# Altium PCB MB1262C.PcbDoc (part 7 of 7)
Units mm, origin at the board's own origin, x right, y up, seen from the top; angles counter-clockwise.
Board outline 208 x 250 mm, 6 copper layers (Top Layer, Layer 2, Layer 3, Layer 4, Layer 5, Bottom Layer), stack 1.596 mm thick; 483 components, 502 nets, 2134 pads, 1709 vias.
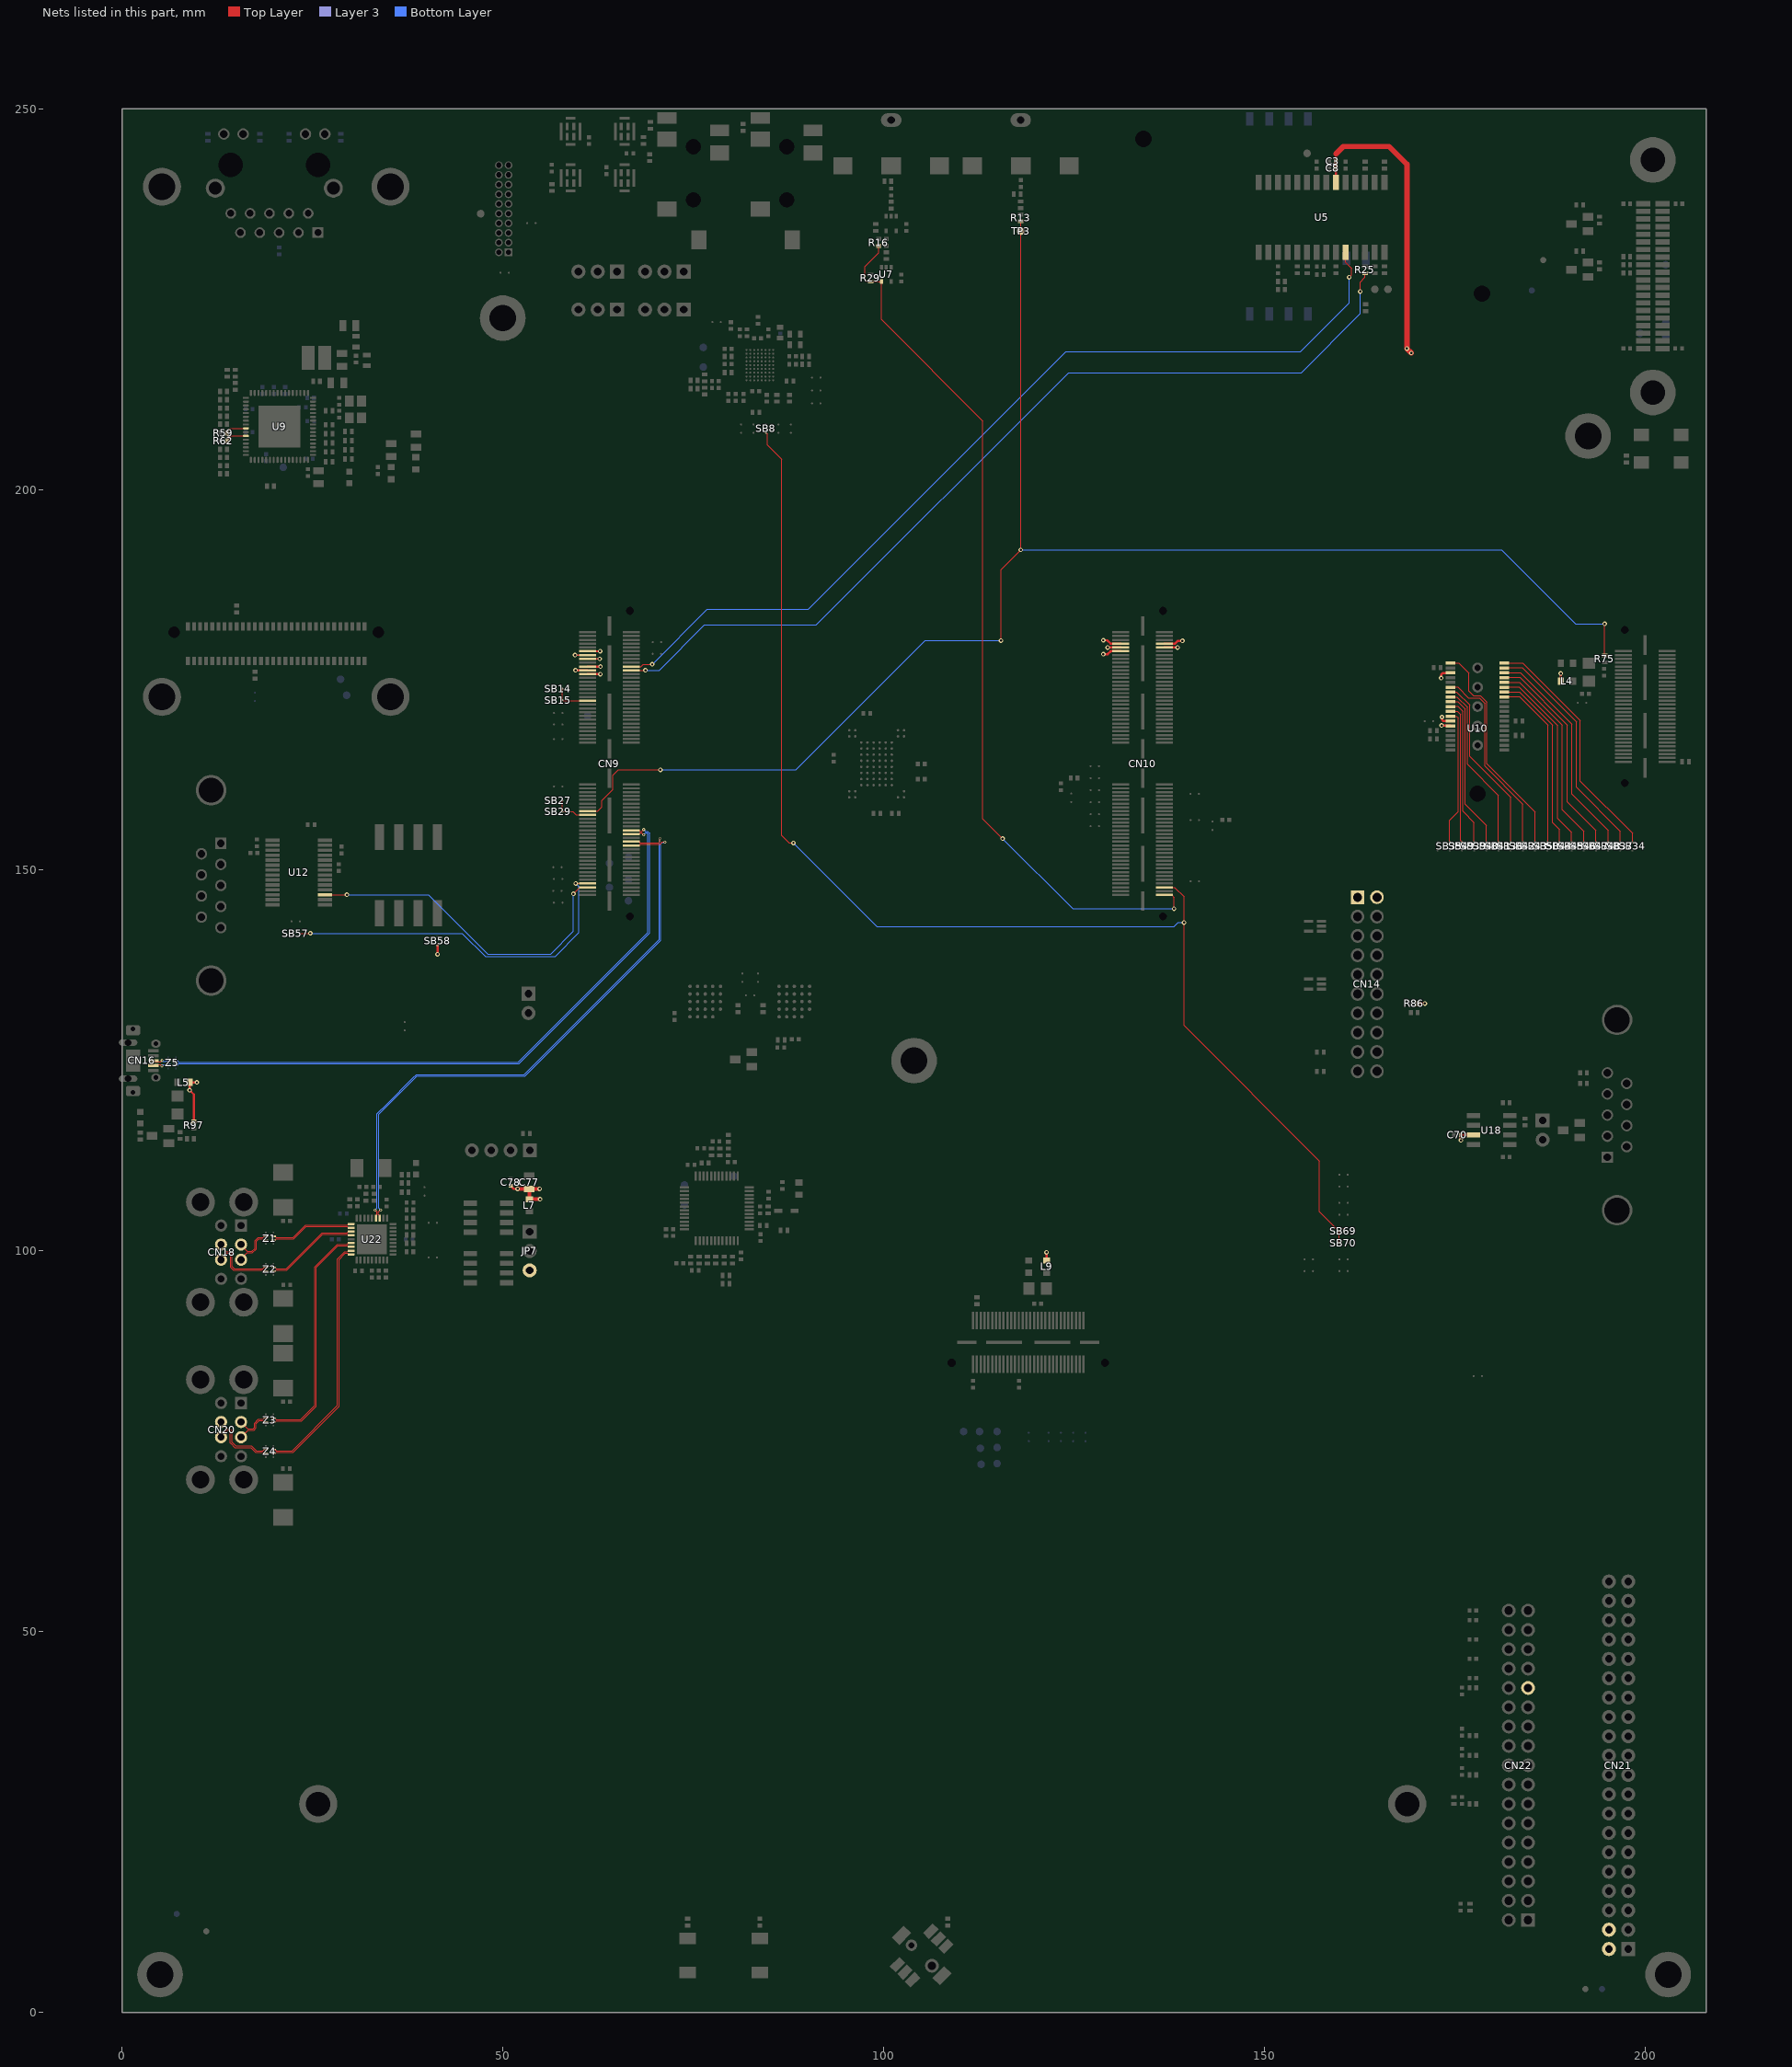
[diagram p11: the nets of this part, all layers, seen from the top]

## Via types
v1: diameter 0.6, hole 0.3, Top Layer to Bottom Layer, tented both sides, 979 vias
v2: diameter 0.55, hole 0.3, Top Layer to Bottom Layer, tented both sides, 687 vias
v3: diameter 0.3, hole 0.15, Top Layer to Bottom Layer, tented both sides, 31 vias
v4: diameter 0.4, hole 0.2, Top Layer to Bottom Layer, tented both sides, 12 vias

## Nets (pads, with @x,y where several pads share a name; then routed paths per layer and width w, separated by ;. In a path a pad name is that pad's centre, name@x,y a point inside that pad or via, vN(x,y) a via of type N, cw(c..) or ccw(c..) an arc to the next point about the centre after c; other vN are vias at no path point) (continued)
SAI2_SDB: CN10.116 SB8.1 SB69.2 SB70.2 | length 168.9
  Top Layer w0.1: SB8.1@84.556,207.434 84.733,207.257 84.733,205.858 86.63,203.961 86.63,154.542 87.605,153.567 v1(88.157,153.567) ; CN10.116@136.87,147.75 136.882,147.738 136.91,147.766 136.929,147.746 138.22,147.746 139.462,146.503 139.437,146.478 v1(139.437,143.128) 139.437,129.621 157.245,111.813 157.245,105.133 159.761,102.618 SB69.2@159.837,102.618 SB70.2@159.836,101.067 ; 160.36,102.937 160.409,102.985
  Bottom Layer w0.1: v1(88.157,153.567) 99.129,142.595 138.158,142.595 138.691,143.128 v1(139.437,143.128)
SAI4_SD_A: CN9.75 R13.1 R75.1 TP3.1 | length 206.1
  Top Layer w0.1: CN9.75@61.13,157.75 62.48,157.75 63.021,158.291 63.021,159.142 64.474,160.595 64.474,162.464 65.186,163.176 v1(70.703,163.176) ; v1(115.416,180.162) 115.416,189.478 v1(118.002,192.065) 118.002,202.486 118,202.489 TP3.1@118,233.925 R13.1@118,235.2 ; R75.1@194.675,178.2 v1(194.675,182.343)
  Bottom Layer w0.1: v1(70.703,163.176) 88.495,163.176 105.478,180.158 115.412,180.158 v1(115.416,180.162) ; v1(118.002,192.065) 181.136,192.065 190.858,182.343 v1(194.675,182.343)
SELRGV: R59.1 U9.25 | length 2.8
  Top Layer w0.1: R59.1@13.775,207.45 13.775,207.513 14.287,208.025 U9.25@16.275,208.025
SMARTCARD_CLK: CN9.20 U5.24 | length 121.1
  Top Layer w0.13: CN9.20@66.87,176.75 68.151,176.75 68.453,177.053 v1(69.618,177.053) ; U5.24@160.675,231.135 160.675,229.827 161.464,229.038 161.464,228.195 v1(161.128,227.86)
  Bottom Layer w0.13: v1(69.618,177.053) 76.843,184.278 90.095,184.278 123.932,218.115 154.743,218.115 161.128,224.5 v1(161.128,227.86)
SMARTCARD_IO: CN9.22 R25.2 | length 120.7
  Top Layer w0.1: CN9.22@66.87,176.25 68.723,176.25 v1(68.728,176.245) ; v1(162.576,226) 162.576,227.224 163.225,227.872 R25.2@163.225,228.4
  Bottom Layer w0.1: v1(68.728,176.245) 70.549,176.245 76.496,182.192 91.176,182.192 124.316,215.332 154.831,215.332 162.576,223.077 v1(162.576,226)
SPDIF_RX: CN10.120 R16.2 R29.2 U7.4 | length 116.4
  Top Layer w0.1: R16.2@99.35,231.975 99.35,231.09 97.531,229.271 97.531,227.554 97.744,227.341 98.259,227.341 R29.2@98.3,227.3 U7.4@99.7,227.3 99.7,222.301 113.026,208.974 113.026,156.758 v1(115.628,154.157) ; CN10.120@136.87,146.75 137.801,146.75 138.131,146.42 v1(138.131,144.936)
  Bottom Layer w0.1: v1(115.628,154.157) 124.849,144.936 v1(138.131,144.936)
TIM2_CH4: CN9.37 SB14.2 SB15.2 | length 4.9
  Top Layer w0.1: SB14.2@57.817,173.842 SB15.2@57.817,172.338 57.905,172.25 CN9.37@61.13,172.25
TIM12_CH1: CN9.77 SB27.2 SB29.2 | length 5
  Top Layer w0.1: SB27.2@57.817,159.163 SB29.2@57.817,157.692 59.209,157.692 59.651,157.25 CN9.77@61.13,157.25
TRACED0: SB43.2 U10.38 | length 29.2
  Top Layer w0.13: U10.38@174.47,177.215 175.505,177.215 176.82,175.9 176.82,173.543 177.428,172.935 178.348,172.935 179.224,172.059 179.224,163.961 185.526,157.659 SB43.2@185.526,153.692
TRACED1: SB42.2 U10.28 | length 25.6
  Top Layer w0.13: U10.28@174.455,174.025 174.47,174.04 175.382,174.04 176.792,172.63 178.205,172.63 178.886,171.949 178.95,171.885 178.95,163.668 183.926,158.692 SB42.2@183.926,153.692
TRACED2: SB36.2 U10.26 | length 23.4
  Top Layer w0.13: U10.26@174.47,173.405 175.231,173.405 176.943,171.693 176.943,164.932 182.326,159.548 SB36.2@182.326,153.692
TRACED3: SB41.2 U10.24 | length 22.2
  Top Layer w0.13: U10.24@174.455,172.755 175.301,172.755 176.654,171.402 176.654,163.914 180.726,159.841 SB41.2@180.726,153.692
TRACED4: SB40.2 U10.22 | length 20.9
  Top Layer w0.13: U10.22@174.47,172.135 174.487,172.118 175.394,172.118 176.336,171.177 176.336,158.659 179.126,155.868 SB40.2@179.126,153.692
TRACED5: SB39.2 U10.20 | length 19.6
  Top Layer w0.13: U10.20@174.455,171.485 174.47,171.5 175.382,171.5 176.047,170.836 176.047,157.748 177.526,156.269 SB39.2@177.526,153.692
TRACED6: SB49.2 U10.18 | length 18.4
  Top Layer w0.13: U10.18@174.394,170.871 174.429,170.906 U10.18@174.47,170.865 ; U10.18@174.455,170.85 175.312,170.85 175.747,170.415 175.747,153.871 SB49.2@175.926,153.692
TRACED7: SB35.2 U10.16 | length 17.9
  Top Layer w0.13: SB35.2@174.326,153.692 174.326,156.581 175.429,157.683 175.429,170.022 175.221,170.23 174.47,170.23 U10.16@174.455,170.215
TRACED8: SB34.2 U10.37 | length 31.9
  Top Layer w0.13: U10.37@181.53,177.215 183.881,177.215 191.461,169.635 191.461,161.706 198.326,154.841 SB34.2@198.326,153.692
TRACED9: SB37.2 U10.35 | length 30.5
  Top Layer w0.13: U10.35@181.53,176.58 183.851,176.58 190.962,169.47 190.962,160.897 196.726,155.132 SB37.2@196.726,153.692
TRACED10: SB48.2 U10.33 | length 29.1
  Top Layer w0.13: U10.33@181.53,175.945 183.621,175.945 190.386,169.18 190.386,159.974 195.126,155.233 SB48.2@195.126,153.692
TRACED11: SB47.2 U10.31 | length 27.8
  Top Layer w0.13: U10.31@181.53,175.31 183.544,175.31 189.771,169.083 189.771,158.969 193.526,155.214 SB47.2@193.526,153.692
TRACED12: SB46.2 U10.29 | length 26.6
  Top Layer w0.13: U10.29@181.53,174.675 183.495,174.675 189.116,169.054 189.116,163.688 ; 189.117,163.869 189.117,157.919 191.926,155.11 SB46.2@191.926,153.692
TRACED13: SB45.2 U10.27 | length 25.1
  Top Layer w0.13: U10.27@181.53,174.04 183.444,174.04 188.481,169.003 188.481,156.823 190.326,154.978 SB45.2@190.326,153.692
TRACED14: SB44.2 U10.25 | length 23.8
  Top Layer w0.13: U10.25@181.53,173.405 183.487,173.405 187.846,169.046 187.846,156.233 188.726,155.352 SB44.2@188.726,153.692
TRACED15: SB50.2 U10.23 | length 22.6
  Top Layer w0.13: U10.23@181.53,172.77 183.495,172.77 187.211,169.054 187.211,153.777 SB50.2@187.126,153.692
TXDLY: R62.1 U9.27 | length 2.8
  Top Layer w0.1: R62.1@13.775,206.375 13.775,206.442 14.358,207.025 U9.27@16.275,207.025
UART4_RX: CN9.115 U12.17 | length 44.3
  Top Layer w0.1: U12.17@26.65,146.775 26.655,146.78 26.797,146.639 26.952,146.793 v1(29.543,146.793) ; v1(59.279,146.896) 60.133,147.75 CN9.115@61.13,147.75
  Bottom Layer w0.1: v1(29.543,146.793) 40.207,146.793 48,139 56.3,139 59.279,141.979 v1(59.279,146.896)
UART4_TX: CN9.113 SB57.1 | length 47.4
  Top Layer w0.1: SB57.1@23.35,141.725 v1(24.736,141.725) ; v1(59.579,148.25) CN9.113@61.13,148.25
  Bottom Layer w0.1: v1(24.736,141.725) 44.675,141.725 47.7,138.7 56.9,138.7 60,141.8 60,147.829 v1(59.579,148.25)
USB1CN25_N: CN18.T2 Z1.2 | length 5.1
  Top Layer w0.1: CN18.T2@15.63,100.85 15.63,100.768 16.451,99.947 17.04,99.947 17.444,100.351 17.444,101.346 17.867,101.769 18.51,101.769 18.665,101.924 Z1.2@18.892,101.924
USB1CN25_P: CN18.T3 Z1.3 | length 5.1
  Top Layer w0.1: CN18.T3@15.704,98.85 15.704,99.01 16.451,99.757 17.119,99.757 17.634,100.272 17.634,101.267 17.946,101.579 18.517,101.579 18.672,101.424 Z1.3@18.892,101.424
  Bottom Layer w0.1: CN18.T3@15.63,98.85 CN18.T3@15.704,98.85
USB2CN25_N: CN18.B2 Z2.2 | length 8.5
  Top Layer w0.1: CN18.B2@13.01,100.85 13.01,100.618 13.694,99.934 14.191,99.934 14.47,99.654 14.47,97.944 14.721,97.694 18.524,97.694 18.679,97.849 Z2.2@18.892,97.849
  Bottom Layer w0.1: CN18.B2@13.01,100.713 CN18.B2@13.01,100.85
USB2CN25_P: CN18.B3 Z2.3 | length 8.5
  Top Layer w0.1: CN18.B3@13.01,98.85 13.01,99.091 13.663,99.744 14.112,99.744 14.28,99.576 14.28,97.865 14.642,97.504 18.518,97.504 18.673,97.349 Z2.3@18.892,97.349
  Bottom Layer w0.1: CN18.B3@13.01,98.85 CN18.B3@13.01,98.928
USB3CN26_N: CN20.T2 Z3.2 | length 4.5
  Top Layer w0.1: CN20.T2@15.63,77.55 16.518,76.662 17.243,76.662 17.408,76.827 17.408,77.394 17.921,77.907 18.518,77.907 18.673,78.062 Z3.2@18.892,78.062
USB3CN26_P: CN20.T3 Z3.3 | length 4.6
  Top Layer w0.1: CN20.T3@15.63,75.55 16.552,76.472 17.321,76.472 17.598,76.749 17.598,77.315 18,77.717 18.503,77.717 18.658,77.562 Z3.3@18.892,77.562
USB4CN26_N: CN20.B2 Z4.2 | length 8.4
  Top Layer w0.1: CN20.B2@13.01,77.55 13.01,77.442 13.803,76.65 14.15,76.65 14.425,76.375 14.425,74.88 14.916,74.389 17.013,74.389 17.62,73.782 18.504,73.782 18.659,73.937 Z4.2@18.892,73.937
USB4CN26_P: CN20.B3 Z4.3 | length 8.5
  Top Layer w0.1: CN20.B3@13.01,75.55 13.01,75.667 13.803,76.46 14.071,76.46 14.235,76.296 14.235,74.801 14.283,74.753 14.837,74.199 16.935,74.199 17.541,73.592 18.505,73.592 18.66,73.437 Z4.3@18.892,73.437
USB_AB_N: CN9.86 Z5.7 | length 85.3
  Top Layer w0.1: CN9.86@66.87,155.25 66.926,155.194 67.917,155.194 68.016,155.095 68.234,155.095 68.488,155.349 v4(68.488,155.354)
  Bottom Layer w0.1: Z5.7@7.074,124.463 7.305,124.463 7.424,124.582 52.109,124.582 69.258,141.731 69.258,154.842 69.007,155.093 68.726,155.093 68.493,155.325 v4@68.463,155.325 ; v4(68.488,155.354) 68.488,155.35 v4@68.463,155.325 ; v4@68.463,155.325 68.453,155.336 68.442,155.325 v4@68.463,155.325
USB_AB_P: CN9.88 Z5.6 | length 84.7
  Top Layer w0.1: CN9.88@66.87,154.75 66.948,154.828 67.96,154.828 68.037,154.905 68.217,154.905 68.478,154.644 v4@68.481,154.648 ; v4(68.481,154.643) v4@68.481,154.648 ; v4@68.488,154.655 v4@68.481,154.648
  Bottom Layer w0.1: Z5.6@7.074,124.963 7.27,124.963 7.46,124.772 52.03,124.772 69.068,141.81 69.068,154.763 68.929,154.903 68.731,154.903 v4@68.481,154.653 ; v4@68.47,154.655 v4@68.472,154.653 ; v4(68.481,154.643) v4@68.481,154.653 ; v4@68.472,154.653 68.477,154.648 v4@68.481,154.653 ; v4@68.472,154.653 68.484,154.664 68.488,154.66 v4@68.481,154.653
USB_CON_N: CN16.2 Z5.2 | length 2.2
  Top Layer w0.1: CN16.2@4.152,124.33 4.326,124.504 5.05,124.504 v4@5.241,124.313
  Bottom Layer w0.1: v4(5.247,124.313) 5.445,124.512 6.026,124.512 Z5.2@6.074,124.463
USB_CON_P: CN16.3 Z5.3 | length 2.2
  Top Layer w0.1: CN16.3@4.125,125 4.27,124.855 5.058,124.855 v4@5.249,125.046
  Bottom Layer w0.1: v4(5.249,125.034) 5.374,124.91 6.022,124.91 Z5.3@6.074,124.963
USB_HUB_N: CN9.94 U22.30 | length 78.5
  Top Layer w0.1: U22.30@33.825,104.3 33.825,104.625 33.67,104.78 33.67,105.12 33.925,105.375 v4(33.95,105.375) ; CN9.94@66.87,153.25 67.9,153.25 68.057,153.407 70.651,153.407 70.929,153.684 70.928,153.686 71.258,153.686 v4(71.261,153.683)
  Bottom Layer w0.1: v4(33.95,105.375) 33.685,105.64 33.685,117.941 38.737,122.993 52.896,122.993 70.717,140.814 70.717,153.458 70.941,153.683 v4(71.261,153.683) ; v4@71.198,153.744 71.244,153.744 71.198,153.79 v4@71.198,153.744
USB_HUB_P: CN9.92 U22.31 | length 78.2
  Top Layer w0.1: v4(33.23,105.375) 33.25,105.375 33.48,105.145 33.48,104.78 33.325,104.625 U22.31@33.325,104.3 ; CN9.92@66.87,153.75 67.881,153.75 68.034,153.597 70.515,153.597 70.64,153.721 70.64,153.791 ; 70.641,153.792 v4(70.641,154.159)
  Bottom Layer w0.1: v4(33.23,105.375) 33.495,105.64 33.495,109.667 33.495,118.019 34.784,119.308 38.186,122.71 38.658,123.183 52.817,123.183 70.527,140.892 70.527,153.578 70.641,153.693 v4(70.641,154.159)
USBDN1_N: U22.1 Z1.7 | length 11
  Top Layer w0.1: Z1.7@19.892,101.924 20.103,101.924 20.257,101.769 22.473,101.769 24.099,103.395 29.574,103.395 29.729,103.55 U22.1@30.075,103.55
USBDN1_P: U22.2 Z1.6 | length 11
  Top Layer w0.1: Z1.6@19.892,101.424 20.109,101.424 20.264,101.579 22.551,101.579 24.177,103.205 29.57,103.205 29.725,103.05 U22.2@30.075,103.05
USBDN2_N: U22.3 Z2.7 | length 12.2
  Top Layer w0.1: Z2.7@19.97,97.857 20.073,97.857 20.24,97.69 21.578,97.69 26.284,102.395 29.57,102.395 29.725,102.55 U22.3@30.075,102.55
USBDN2_P: U22.4 Z2.6 | length 12.2
  Top Layer w0.1: Z2.6@19.961,97.345 20.101,97.345 20.255,97.5 21.657,97.5 26.362,102.205 29.595,102.205 29.75,102.05 U22.4@30.075,102.05
USBDN3_N: U22.6 Z3.7 | length 30.5
  Top Layer w0.1: Z3.7@19.892,78.062 20.092,78.062 20.272,77.882 23.468,77.882 25.307,79.721 25.307,97.937 28.265,100.895 29.563,100.895 29.718,101.05 U22.6@30.075,101.05
USBDN3_P: U22.7 Z3.6 | length 30.5
  Top Layer w0.1: Z3.6@19.892,77.562 20.106,77.562 20.236,77.692 23.547,77.692 25.497,79.642 25.497,97.858 28.344,100.705 28.943,100.705 29.564,100.705 29.719,100.55 U22.7@30.075,100.55
USBDN4_N: U22.8 Z4.7 | length 32.4
  Top Layer w0.1: Z4.7@19.892,73.937 20.1,73.937 20.26,73.777 22.374,73.777 28.301,79.704 28.301,98.953 29.243,99.895 29.573,99.895 29.728,100.05 U22.8@30.075,100.05
USBDN4_P: U22.9 Z4.6 | length 32.4
  Top Layer w0.1: Z4.6@19.892,73.437 20.104,73.437 20.253,73.587 22.452,73.587 28.491,79.625 28.491,98.874 29.321,99.705 29.589,99.705 29.744,99.55 U22.9@30.075,99.55
VBUS_OTG: CN9.11 CN9.13 CN9.15 L5.1 R97.2 | length 11.3
  Top Layer w0.2: v1(59.485,178.25) CN9.13@61.13,178.25 ; CN9.15@61.13,177.75 v1(62.719,177.75) ; CN9.11@61.13,178.75 v1(62.77,178.75)
  Top Layer w0.3: R97.2@9.42,116.928 9.436,116.944 9.436,120.561 v1(8.874,121.122) L5.1@8.874,122.143 v1(9.828,122.143)
VBUS_SW: CN9.19 CN9.21 CN9.23 JP7.3 | length 5
  Top Layer w0.3: v1(59.535,176.25) CN9.21@61.13,176.25 ; CN9.23@61.13,175.75 v1(62.812,175.75) ; CN9.19@61.13,176.75 v1(62.825,176.75)
VDD: CN10.8 CN10.10 CN14.1 CN14.2 R86.1 U10.12 U10.14 U10.34 | length 10.1
  Top Layer w0.3: CN10.10@136.87,179.25 136.873,179.253 v1(138.607,179.253) ; CN10.8@136.87,179.75 138.265,179.75 138.63,180.115 139.153,180.115 v1@139.225,180.187 ; v1@139.192,180.22 v1@139.225,180.187 ; v1(139.226,180.111) v1@139.226,180.186 ; R86.1@170.125,132.5 v1(171.059,132.5) ; v1(173.195,175.238) 173.195,175.658 173.423,175.886 174.48,175.886 174.505,175.91 U10.34@174.47,175.945 ; v1(173.26,169.01) 174.42,169.01 U10.12@174.47,168.96 ; v1(173.311,170.111) 173.311,169.755 173.471,169.595 U10.14@174.47,169.595 ; v1@139.225,180.187 v1@139.226,180.186 ; v1@139.225,180.187 139.226,180.188 v1@139.226,180.186
  Layer 3 w0.3: v1(138.607,179.253) v1@138.618,179.242 ; v1@173.192,175.235 v1(173.195,175.238) ; v1@173.26,170.06 v1(173.311,170.111)
VIN: C3.2 C8.2 C70.2 C77.2 C78.2 CN10.7 CN10.9 CN10.11 CN21.2 CN21.4 CN22.25 L4.2 L7.1 L9.1 SB58.2 U5.6 U18.3 | length 58.6
  Top Layer w0.3: v1(41.425,138.955) SB58.2@41.425,140.15 ; C78.2@51.041,108.557 51.45,108.147 v1@51.96,108.147 ; L9.1@121.4,98.75 v1@121.4,99.786 ; v1(128.835,180.197) 129.354,180.197 129.8,179.75 CN10.7@131.13,179.75 ; v1(128.843,178.363) 129.426,178.363 129.813,178.75 CN10.11@131.13,178.75 ; v1(129.418,179.253) 131.133,179.253 CN10.9@131.13,179.25 ; 159.4,243.983 C8.2@159.4,242.175 159.405,242.17 U5.6@159.405,240.315 ; v1(175.796,114.524) 175.775,114.545 C70.2@175.775,115.25 177.44,115.25 U18.3@177.45,115.24 ; v1(188.907,175.834) 188.925,175.817 L4.2@188.925,174.825
  Top Layer w0.5: v1(51.94,108.15) C77.2@53.458,108.15 C77.2@53.48,108.15 ; C77.2@53.498,108.223 53.48,108.205 C77.2@53.48,108.15 ; v1(54.828,108.15) C77.2@53.48,108.15 ; v1(54.888,106.8) L7.1@53.48,106.8 C77.2@53.48,108.15 ; 159.4,243.983 159.402,243.985 159.402,244.067
  Top Layer w0.7: 159.402,244.067 160.359,245.024 166.375,245.024 168.704,242.695 v1(168.704,218.491) v1(169.283,217.912)
  other v1: 121.4,99.82
pads on no net: B1.MT1 B1.MT2 CN3.17 CN3.18 CN4.5 CN4.7 CN4.MT1 CN4.MT2 CN5.5 CN5.7 CN5.MT1 CN5.MT2 CN6.3 CN6.5 CN6.9 CN6.11 CN6.15 CN6.17 CN6.21 CN6.27 CN6.29 CN6.30 CN6.33 CN6.35 CN6.39 CN6.41 CN6.45 CN6.47 CN6.NHP2 CN6.NPH1 CN6.PTH1 CN6.PTH2 CN6.PTH3 CN6.PTH4 CN8.8 CN8.9 CN8.11 CN8.13 CN8.14 CN8.15 CN8.16 CN8.17 CN8.18 CN9.14 CN9.16 CN9.18 CN9.35 CN9.55 CN9.67 CN9.73 CN9.83 CN9.85 CN9.102 CN9.106 CN9.110 CN9.114 CN9.117 CN9.118 CN9.119 CN9.129 CN9.130 CN10.1 CN10.3 CN10.5 CN10.6 CN10.12 CN10.13 CN10.18 CN10.19 CN10.21 CN10.22 CN10.23 CN10.25 CN10.92 CN10.94 CN10.119 CN10.129 CN10.130 CN11.3 CN11.5 CN11.8 CN11.11 CN11.12 CN11.15 CN11.16 CN11.19 CN11.20 CN11.32 CN11.35 CN11.36 CN11.43 CN11.44 CN11.45 CN11.52 CN11.59 CN11.65 CN11.66 CN12.1 CN12.4 CN12.7 CN12.9 CN13.2 CN13.6 CN15.1 CN15.4 CN15.8 CN16.11 CN16.12 CN19.2 CN19.20 CN19.22 CN19.24 CN19.25 CN19.26 CN19.28 CN19.30 CN19.31 CN19.33 CN19.34 CN19.35 CN19.37 CN19.38 CN19.39 CN19.41 CN19.42 CN19.43 CN19.45 CN19.47 CN19.51 CN19.55 CN19.59 CN19.65 CN19.66 CN19.PTH3 CN19.PTH4 CN23.11 CN23.12 CN23.C6 MIRE1.1 MIRE2.1 MIRE3.1 MIRE4.1 MIRE5.1 MIRE6.1 U1.6 U1.7 U1.8 U2.6 U2.7 U2.8 U3.6 U3.7 U3.8 U4.6 U4.7 U4.8 U5.25 U6.1 U7.1 U8.A6 U8.A8 U8.B1 U8.B4 U8.B7 U8.B8 U8.C3 U8.C4 U8.C7 U8.C8 U8.F5 U8.F6 U8.F8 U8.F9 U8.G4 U8.H3 U8.H4 U8.H5 U9.16 U9.17 U9.32 U9.43 U9.44 U9.45 U9.46 U9.47 U10.1 U10.2 U10.3 U10.4 U10.MT6 U11.A1 U11.A2 U11.A9 U11.A10 U11.B1 U11.B9 U11.B10 U11.D6 U11.D7 U11.D8 U11.E3 U11.E4 U11.E5 U11.E6 U11.E7 U11.E8 U11.F3 U11.F4 U11.F5 U11.F6 U11.F7 U11.F8 U11.G3 U11.G5 U11.G6 U11.G7 U11.G8 U11.H3 U11.H5 U11.H6 U11.H7 U11.J3 U11.J5 U11.L1 U11.L2 U11.L9 U11.L10 U11.M1 U11.M2 U11.M9 U11.M10 U12.4 U12.8 U12.9 U12.11 U12.12 U12.14 U12.15 U12.16 U12.18 U12.19 U12.20 U12.21 U13.1 U13.3 U14.A2 U14.A3 U14.A5 U14.B1 U14.B5 U14.C1 U14.C3 U14.C5 U14.D1 U14.D5 U14.E1 U14.E2 U14.E3 U14.E4 U14.E5 U15.A2 U15.A3 U15.A5 U15.B1 U15.B5 U15.C1 U15.C3 U15.C5 U15.D1 U15.D5 U15.E1 U15.E2 U15.E3 U15.E4 U15.E5 U20.3 U20.4 U20.5 U20.6 U20.25 U20.32 U20.38 U20.41 X1.2 X1.4
copper on no net: | length 0.8
  Top Layer w0.3: v1(19.041,197.738) 19.041,198.514

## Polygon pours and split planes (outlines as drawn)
GND on Top Layer "gnd_top" (solid, remove dead copper, pour order 76): 208,250 0,250 0,0 208,0
1V05_GMII on Top Layer "1V05_GMII_L01_P031" (solid, pour order 31): 32.668,219.514 33.129,219.052 33.129,217.286 32.864,217.021 27.69,217.021 27.69,218.975 28.229,219.514
2V8 on Layer 4 "2V8_L04_P038" (solid, pour order 38): 64.247,237.407 64.247,178.615 64.247,178.325 64.661,177.912 65.143,177.429 67.076,177.429 81.5,191.854 81.5,220 94.536,233.036 185.643,233.036 192.15,226.529 197.543,226.529 197.543,217.402 198.167,216.778 203.607,216.778 206.703,219.874 206.703,244.627 203.379,247.95 74.771,247.95
1V8 on Layer 4 "1V8_L04_P034" (solid, pour order 34): 197.881,204.185 198.608,204.913 198.608,209.579 197.192,210.995 197.192,218.286 202.311,223.405 202.311,232.386 202.311,237.616 201.089,238.838 197.965,238.838 195.948,236.822 195.948,228.051 194.101,226.204 191.899,226.204 185.717,232.386 94.661,232.386 81.882,219.607 81.882,203.636 107.874,177.645 108.985,176.534 108.985,176.02 108.973,105.815 108.973,82 110.671,80.302 113.564,80.302 118.48,85.218 118.48,127.957 118.48,176.249 123.254,181.023 136.364,181.023 137.274,180.114 138.384,180.114 140.554,182.284 161.19,182.284 163.279,184.372 163.279,217.667 165.664,220.052 174.509,220.052 190.225,204.185
VIN on Layer 4 "VIN_L04_P039" (solid, pour order 39): 166.053,219.008 174.254,219.008 205.213,188.049 205.213,123.454 205.213,0.558 95.732,0.558 56.216,40.073 56.216,105.286 40.778,120.724 40.778,139.019 41.725,139.967 49.53,139.967 110.123,79.373 113.663,79.373 119.317,85.027 119.317,176.108 123.051,179.842 123.738,180.529 130.765,180.529 136.192,180.529 138.616,178.106 141.427,178.106 158.454,161.078 158.454,159.514 158.454,138.131 159.06,137.525 166.332,130.253 170.921,130.253 173.431,130.253 175.249,132.071 175.163,132.158 175.163,177.348 164.296,188.215 164.296,217.25
1V05_DVDD_GMII on Layer 4 "1V05_DVDD_GMII_L04_P063" (solid, pour order 63): 16.759,203.984 16.268,203.494 16.268,201.325 21.098,196.494 37.291,196.494 40.423,199.626 40.423,210.13 33.686,216.866 33.386,216.866 32.118,216.866 31.717,216.466 31.65,216.399 31.65,210.128 35.24,206.539 35.24,202.416 34.814,201.99 33.05,201.99 31.917,203.123 20.184,203.123 19.322,203.984
VDD on Layer 4 "VDD_L04_P037" (solid, pour order 37): 140.495,181.778 169.105,181.778 174.054,176.829 174.054,132.853 173.302,132.101 172.818,131.617 170.506,131.617 170.237,131.617 169.108,132.746 167.334,134.52 167.334,141.455 167.334,142.799 166.098,144.035 165.028,145.105 160.62,145.105 159.573,146.152 159.573,160.775 144.432,175.915 141.643,178.705 138.854,178.705 138.531,178.705 138.181,179.055 138.181,179.464
VBUS_OTG on Layer 4 "VBUS_OTG_L04_P055" (solid, pour order 55): 8.489,123.493 7.997,123.004 7.997,121.148 8.461,120.685 8.917,120.685 58.756,170.524 58.756,176.744 59.147,177.135 59.38,177.368 63.008,177.368 63.428,177.789 63.428,177.851 63.428,179.159 62.524,180.063 59.858,180.063 8.628,128.833 8.628,124.787 8.628,123.633
VBUS_SW on Layer 4 "VBUS_SW_L04_P047" (solid, pour order 47): 52.273,94.628 54.313,94.628 55.606,95.921 55.606,105.055 55.239,105.422 40.127,120.534 40.127,123.182 40.127,141.069 63.58,164.523 63.58,176.678 63.192,177.066 59.64,177.066 59.116,176.542 59.116,170.229 30.98,142.094 30.98,119.559 44.711,105.828 47.48,105.828 48.714,104.594 48.714,97.706
3V3_AVDD_GMII on Layer 4 "3V3_AVDD_GMII_L04_P033" (solid, pour order 33): 20.178,212.155 21.803,210.53 22.815,210.53 24.208,210.53 24.231,210.507 24.877,209.861 24.877,209.027 25.624,208.28 32.923,208.28 34.915,206.288 34.915,202.592 34.721,202.398 33.09,202.398 32.775,202.713 32.008,203.48 20.458,203.48 18.923,205.016 18.923,211.308 19.77,212.155
1V05_AVDD_GMII on Layer 4 "1V05_AVDD_GMII_L04_P062" (solid, pour order 62): 31.057,219.675 31.057,209.329 30.32,208.592 25.68,208.592 25.171,209.101 25.171,210.039 24.351,210.859 21.916,210.859 20.32,212.455 19.622,212.455 18.637,211.47 18.086,211.47 17.871,211.685 17.871,213.364 28.047,223.54 28.081,223.573 31.418,223.573 32.553,222.439 32.553,221.171
NetC99_2 on Layer 4 "NETC99_2_L04_P053" (solid, pour order 53): 46.212,105.454 47.18,105.454 48.052,104.582 48.052,101.686 36.732,90.366 35.362,90.367 19.41,90.367 16.746,93.031 16.746,99.937 16.746,105.752 16.059,106.439 15.933,106.565 15.296,106.565 14.395,105.665 14.395,102.813 13.779,102.197 12.388,102.197 11.775,102.81 11.775,103.044 11.775,109.688 12.757,110.671 13.202,111.115 17.612,111.115 18.665,111.115 20.419,109.361 20.419,105.709 19.303,104.593 19.303,98.799 22.768,95.334 37.784,95.334 45.131,102.681 45.131,104.46 45.685,105.014 46.125,105.454 46.265,105.454
NetC76_1 on Layer 4 "NETC76_1_L04_P051" (solid, pour order 51): 44.796,104.371 44.796,103.073 37.661,95.939 28.417,95.939 25.792,95.939 20.131,101.599 20.131,104.318 21.722,105.908 23.954,105.908 30.088,99.775 31.809,99.775 35.67,99.775 40.635,104.74 44.427,104.74
NetC102_1 on Layer 4 "NETC102_1_L04_P049" (solid, pour order 49): 45.138,96.984 45.138,93.79 29.51,78.162 20.865,78.162 20.776,78.162 19.921,79.017 19.921,80.347 21.611,82.037 28.777,82.037 43.374,96.633 44.264,97.523 44.609,97.523
NetC106_2 on Layer 4 "NETC106_2_L04_P045" (solid, pour order 45): 46.453,98.653 46.66,98.86 47.277,98.86 48.166,97.971 48.166,97.211 48.166,90.878 25.924,68.635 22.321,68.635 20.624,68.635 16.707,72.553 16.707,81.783 16.651,81.84 15.035,81.84 14.477,81.282 14.477,79.553 13.774,78.85 12.219,78.85 11.553,79.515 11.553,84.99 11.553,86.316 12.092,86.855 12.776,87.539 17.169,87.539 18.129,87.539 19.47,86.198 20.077,85.591 20.077,82.033 19.28,81.236 19.28,72.766 19.84,72.206 24.195,72.206 45.466,93.477 45.466,97.667
3V3 on Layer 3 "3V3_L03_P064" (solid, pour order 64): 205.737,247.986 205.737,4.658 205.737,2.461 2.993,2.461 2.993,6.677 2.993,244.446 2.993,247.986 6.533,247.986
3V3_DVDD_GMII on Layer 3 "3V3_DVDD_GMII_L03_P032" (solid, pour order 32): 39.17,241.972 39.17,205.268 34.054,200.152 12.414,200.152 9.502,203.064 9.502,244.013 11.968,246.478 34.663,246.478
GND on Bottom Layer "GND_L06_P073" (solid, remove dead copper, pour order 73): 208,250 208,0 0,0 0,59.478 0,250
NetC102_1 on Bottom Layer "NETC102_1_L06_P069" (solid, pour order 69): 23.614,81.667 23.614,80.62 22.043,79.049 16.351,79.049 16.172,79.228 16.172,81.086 19.592,81.086 20.502,81.997 23.284,81.997
NetC76_1 on Bottom Layer "NETC76_1_L06_P067" (solid, pour order 67): 23.756,105.382 23.756,104.066 21.965,102.276 14.945,102.276 14.692,102.529 14.692,104.563 19.763,104.563 20.978,105.778 23.361,105.778
GND on Layer 2 "GND_L02_P044" (solid, pour order 44): 0,250 0,0 208,0 208,250
GND on Layer 5 "GND_L05_P075" (solid, remove dead copper, pour order 75): 208,250 208,0 0,0 0,250

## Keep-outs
Keep-Out Layer:
  the board outline again, w0.1
  text "BOARD OUTLINE" at 83.125,-20.375 h1.9

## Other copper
Top Layer:
  text "1" at 12.773,4.071 h1
  text "1" at 96.4,-15.25 h2
  text "PRIMARY SIDE" at 82.11,-20.33 h2
Layer 4:
  text "4" at 15.315,4.09 h1
  text "4" at 96.4,-15.25 h2
  text "LAYER 4 (VCC PLANE)" at 82.11,-20.33 h2
Layer 5:
  text "5" at 16.319,4.105 h1
  text "5" at 96.4,-15.25 h2
  text "LAYER 5 (GND PLANE)" at 82.11,-20.33 h2
Layer 2:
  text "2" at 13.418,4.076 h1
  text "2" at 96.4,-15.25 h2
  text "LAYER 2 (GND PLANE)" at 82.11,-20.33 h2
Layer 3:
  text "3" at 14.374,4.066 h1
  text "3" at 96.4,-15.25 h2
  text "LAYER 3" at 82.11,-20.33 h2
Bottom Layer:
  text "6" at 17.926,4.097 h1
  text "6" at 96.4,-15.25 h2
  text "SECONDARY SIDE" at 82.11,-20.33 h2
Multi-Layer:
  circle w0.2: c-17,265.064 r3.442
  circle w0.2: c-17,265.064 r1.922
  circle w0.2: c231,266.063 r3.442
  circle w0.2: c231,266.063 r1.922
  circle w0.2: c226,-10.937 r3.442
  circle w0.2: c226,-10.937 r1.922
  pour cut-out: 12.303,5.554 12.303,3.554 18.691,3.554 18.691,5.554
  lines w0.2: -22.969,265 -10.967,265 ; -17,258.968 -17,270.969 ; 220.031,-11 232.033,-11 ; 225.031,266 237.033,266 ; 226,-17.033 226,-5.031 ; 231,259.967 231,271.969

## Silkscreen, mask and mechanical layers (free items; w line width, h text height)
Top Overlay:
  drawing of 1502 lines, arcs and shapes, not listed
  text "Headset" at 92.824,231.935 h2 r90
  text "2" at 47.569,230.544 h1.2
  text "Ethernet" at 12.067,229.006 h2
  text "Mems Micro" at 42.653,227.947 h2 r90
  text "Speaker_out" at 80.407,226.363 h2 r90
  text "SPDIF input" at 107.651,225.626 h2 r90
  text "Camera" at 206.407,224.212 h2 r90
  text "SPDIF output" at 123.496,223.781 h2 r90
  text "Trace" at 174.31,184.79 h2
  text "LTDC" at 196.561,182.912 h2
  text "Ethernet Module" at 9.225,171.956 h2
  text "2" at 173.26,164.005 h1.2
  text "UART4" at 2.813,163.83 h2
  text "I2C_EXT" at 32.434,158.131 h2
  text "JTAG" at 160.295,152.732 h2
  text "CAN FD" at 195.38,133.784 h2
  text "USB_OTG" at 6.213,124.209 h2
  text "MFX" at 44.875,115.15 h2
  text "USB_Host" at 3.655,109.569 h2
  text "DSI" at 103.916,87.357 h2
  text "USB_Host" at 3.348,65.469 h2
  text "Motor control" at 190.667,23.76 h2 r90
  text "GPIO expansion" at 202.043,22.112 h2 r90
  text "Joystick" at 99.289,13.027 h2
  text "Reset" at 75.359,12.156 h2
  text "2" at 177.761,9.864 h1.2
  text "STM32MP15X-EVAL" at 128.439,7.495 h2
  text "MB1262C" at 36.677,7.47 h2
  text "SILKSCREEN, (PRIMARY)" at 82.11,-20.33 h2
Bottom Overlay:
  lines w0.2: 50,22 60,22 77,22 77,32 50,32 50,22
  text "Smart Card" at 181.923,216.424 h2
  text "MB1262C" at 69.119,34.148 h2
  text "SILKSCREEN, (SECONDARY)" at 122.87,-20.33 h2
Top Paste:
  text "SOLDER PASTE, (PRIMARY)" at 82.11,-20.33 h2
Bottom Paste:
  text "SOLDER PASTE, (SECONDARY)" at 81.56,-20.33 h2
Top Solder:
  text "SOLDER MASK, (PRIMARY)" at 82.11,-20.33 h2
Bottom Solder:
  text "SOLDER MASK, (SECONDARY)" at 82.11,-20.33 h2
Mechanical 2:
  circle w0.2: c-17,265.064 r3.442
  circle w0.2: c-17,265.064 r1.922
  circle w0.2: c231,266.063 r3.442
  circle w0.2: c231,266.063 r1.922
  circle w0.2: c226,-10.937 r3.442
  circle w0.2: c226,-10.937 r1.922
  lines w0.2: -22.969,265 -10.967,265 ; -17,258.968 -17,270.969 ; 220.031,-11 232.033,-11 ; 225.031,266 237.033,266 ; 226,-17.033 226,-5.031 ; 231,259.967 231,271.969
Drill Drawing:
  drawing of 557 lines, arcs and shapes, not listed
  text "Layer" at 225.612,245.218 h2
  text "Name" at 236.954,245.218 h2
  text "Material" at 262.178,245.218 h2
  text "Thickness" at 283.993,245.218 h2
  text "Constant" at 300.962,245.218 h2
  text "Board Layer Stack" at 317.121,245.218 h2
  text "1" at 225.612,241.218 h2
  text "Top Overlay" at 236.954,241.218 h2
  text "2" at 225.612,237.218 h2
  text "Top Solder" at 236.954,237.218 h2
  text "Solder Resist" at 262.178,237.218 h2
  text "0,010mm" at 283.993,237.218 h2
  text "3,5" at 300.962,237.218 h2
  text "3" at 225.612,233.218 h2
  text "Top Layer" at 236.954,233.218 h2
  text "Copper" at 262.178,233.218 h2
  text "0,042mm" at 283.993,233.218 h2
  text "4" at 225.612,229.218 h2
  text "Dielectric 1" at 236.954,229.218 h2
  text "FR4" at 262.178,229.218 h2
  text "0,093mm" at 283.993,229.218 h2
  text "4,2" at 300.962,229.218 h2
  text "5" at 225.612,225.218 h2
  text "Layer 2" at 236.954,225.218 h2
  text "Copper" at 262.178,225.218 h2
  text "0,035mm" at 283.993,225.218 h2
  text "6" at 225.612,221.218 h2
  text "Dielectric 2" at 236.954,221.218 h2
  text "FR4" at 262.178,221.218 h2
  text "0,100mm" at 283.993,221.218 h2
  text "4,2" at 300.962,221.218 h2
  text "7" at 225.612,217.218 h2
  text "Layer 3" at 236.954,217.218 h2
  text "Copper" at 262.178,217.218 h2
  text "0,035mm" at 283.993,217.218 h2
  text "8" at 225.612,213.218 h2
  text "Dielectric 3" at 236.954,213.218 h2
  text "FR4" at 262.178,213.218 h2
  text "0,986mm" at 283.993,213.218 h2
  text "4,2" at 300.962,213.218 h2
  text "9" at 225.612,209.218 h2
  text "Layer 4" at 236.954,209.218 h2
  text "Copper" at 262.178,209.218 h2
  text "0,035mm" at 283.993,209.218 h2
  text "10" at 225.612,205.218 h2
  text "Dielectric 4" at 236.954,205.218 h2
  text "FR4" at 262.178,205.218 h2
  text "0,100mm" at 283.993,205.218 h2
  text "4,2" at 300.962,205.218 h2
  text "11" at 225.612,201.218 h2
  text "Layer 5" at 236.954,201.218 h2
  text "Copper" at 262.178,201.218 h2
  text "0,035mm" at 283.993,201.218 h2
  text "12" at 225.612,197.218 h2
  text "Dielectric 5" at 236.954,197.218 h2
  text "FR4" at 262.178,197.218 h2
  text "0,093mm" at 283.993,197.218 h2
  text "4,2" at 300.962,197.218 h2
  text "13" at 225.612,193.218 h2
  text "Bottom Layer" at 236.954,193.218 h2
  text "Copper" at 262.178,193.218 h2
  text "0,042mm" at 283.993,193.218 h2
  text "14" at 225.612,189.218 h2
  text "Bottom Solder" at 236.954,189.218 h2
  text "Solder Resist" at 262.178,189.218 h2
  text "0,010mm" at 283.993,189.218 h2
  text "3,5" at 300.962,189.218 h2
  text "15" at 225.612,185.218 h2
  text "Bottom Overlay" at 236.954,185.218 h2
  text "Symbol" at 228.045,161.77 h1.83
  text "Count" at 240.894,161.77 h1.83
  text "Hole Size" at 257.4,161.77 h1.83
  text "Plated" at 287.109,161.77 h1.83
  text "Hole Type" at 299.959,161.77 h1.83
  text "Via/Pad" at 318.597,161.77 h1.83
  text "Hole Length" at 333.579,161.77 h1.83
  text "Routed Path Length" at 362.019,161.77 h1.83
  text "31" at 240.894,157.96 h1.52
  text "0,150mm (5,91mil)" at 257.4,157.96 h1.52
  text "PTH" at 287.109,157.96 h1.52
  text "Round" at 299.959,157.96 h1.52
  text "Via" at 318.597,157.96 h1.52
  text "-" at 333.579,157.96 h1.52
  text "-" at 362.019,157.96 h1.52
  text "12" at 240.894,154.15 h1.52
  text "0,200mm (7,87mil)" at 257.4,154.15 h1.52
  text "PTH" at 287.109,154.15 h1.52
  text "Round" at 299.959,154.15 h1.52
  text "Via" at 318.597,154.15 h1.52
  text "-" at 333.579,154.15 h1.52
  text "-" at 362.019,154.15 h1.52
  text "1666" at 240.894,150.34 h1.52
  text "0,300mm (11,81mil)" at 257.4,150.34 h1.52
  text "PTH" at 287.109,150.34 h1.52
  text "Round" at 299.959,150.34 h1.52
  text "Via" at 318.597,150.34 h1.52
  text "-" at 333.579,150.34 h1.52
  text "-" at 362.019,150.34 h1.52
  text "2" at 240.894,146.53 h1.52
  text "0,600mm (23,62mil)" at 257.4,146.53 h1.52
  text "PTH" at 287.109,146.53 h1.52
  text "Slot" at 299.959,146.53 h1.52
  text "Pad" at 318.597,146.53 h1.52
  text "1,300mm (51,18mil)" at 333.579,146.53 h1.52
  text "0,700mm (27,56mil)" at 362.019,146.53 h1.52
  text "2" at 240.894,142.72 h1.52
  text "0,650mm (25,59mil)" at 257.4,142.72 h1.52
  text "PTH" at 287.109,142.72 h1.52
  text "Slot" at 299.959,142.72 h1.52
  text "Pad" at 318.597,142.72 h1.52
  text "0,850mm (33,47mil)" at 333.579,142.72 h1.52
  text "0,200mm (7,88mil)" at 362.019,142.72 h1.52
  text "20" at 240.894,138.91 h1.52
  text "0,700mm (27,56mil)" at 257.4,138.91 h1.52
  text "PTH" at 287.109,138.91 h1.52
  text "Round" at 299.959,138.91 h1.52
  text "Pad" at 318.597,138.91 h1.52
  text "-" at 333.579,138.91 h1.52
  text "-" at 362.019,138.91 h1.52
  text "1" at 240.894,135.1 h1.52
  text "0,800mm (31,50mil)" at 257.4,135.1 h1.52
  text "NPTH" at 287.109,135.1 h1.52
  text "Round" at 299.959,135.1 h1.52
  text "Pad" at 318.597,135.1 h1.52
  text "-" at 333.579,135.1 h1.52
  text "-" at 362.019,135.1 h1.52
  text "I" at 227.588,134.846 h1.69
  text "5" at 240.894,131.29 h1.52
  text "0,810mm (31,89mil)" at 257.4,131.29 h1.52
  text "PTH" at 287.109,131.29 h1.52
  text "Round" at 299.959,131.29 h1.52
  text "Pad" at 318.597,131.29 h1.52
  text "-" at 333.579,131.29 h1.52
  text "-" at 362.019,131.29 h1.52
  text "B" at 227.306,131.036 h1.69
  text "2" at 240.894,127.48 h1.52
  text "0,850mm (33,47mil)" at 257.4,127.48 h1.52
  text "NPTH" at 287.109,127.48 h1.52
  text "Slot" at 299.959,127.48 h1.52
  text "Pad" at 318.597,127.48 h1.52
  text "2,425mm (95,47mil)" at 333.579,127.48 h1.52
  text "1,575mm (62,01mil)" at 362.019,127.48 h1.52
  text "10" at 240.894,123.67 h1.52
  text "0,900mm (35,43mil)" at 257.4,123.67 h1.52
  text "PTH" at 287.109,123.67 h1.52
  text "Round" at 299.959,123.67 h1.52
  text "Pad" at 318.597,123.67 h1.52
  text "-" at 333.579,123.67 h1.52
  text "-" at 362.019,123.67 h1.52
  text "16" at 240.894,119.86 h1.52
  text "0,920mm (36,22mil)" at 257.4,119.86 h1.52
  text "PTH" at 287.109,119.86 h1.52
  text "Round" at 299.959,119.86 h1.52
  text "Pad" at 318.597,119.86 h1.52
  text "-" at 333.579,119.86 h1.52
  text "-" at 362.019,119.86 h1.52
  text "85" at 240.894,116.05 h1.52
  text "1,000mm (39,37mil)" at 257.4,116.05 h1.52
  text "PTH" at 287.109,116.05 h1.52
  text "Round" at 299.959,116.05 h1.52
  text "Pad" at 318.597,116.05 h1.52
  text "-" at 333.579,116.05 h1.52
  text "-" at 362.019,116.05 h1.52
  text "2" at 240.894,112.24 h1.52
  text "1,000mm (39,37mil)" at 257.4,112.24 h1.52
  text "PTH" at 287.109,112.24 h1.52
  text "Slot" at 299.959,112.24 h1.52
  text "Pad" at 318.597,112.24 h1.52
  text "1,600mm (62,99mil)" at 333.579,112.24 h1.52
  text "0,600mm (23,62mil)" at 362.019,112.24 h1.52
  text "F" at 227.306,111.986 h1.69
  text "8" at 240.894,108.43 h1.52
  text "1,050mm (41,34mil)" at 257.4,108.43 h1.52
  text "NPTH" at 287.109,108.43 h1.52
  text "Round" at 299.959,108.43 h1.52
  text "Pad" at 318.597,108.43 h1.52
  text "-" at 333.579,108.43 h1.52
  text "-" at 362.019,108.43 h1.52
  text "A" at 227.306,108.176 h1.69
  text "1" at 240.894,104.62 h1.52
  text "1,100mm (43,31mil)" at 257.4,104.62 h1.52
  text "NPTH" at 287.109,104.62 h1.52
  text "Round" at 299.959,104.62 h1.52
  text "Pad" at 318.597,104.62 h1.52
  text "-" at 333.579,104.62 h1.52
  text "-" at 362.019,104.62 h1.52
  text "34" at 240.894,100.81 h1.52
  text "1,100mm (43,31mil)" at 257.4,100.81 h1.52
  text "PTH" at 287.109,100.81 h1.52
  text "Round" at 299.959,100.81 h1.52
  text "Pad" at 318.597,100.81 h1.52
  text "-" at 333.579,100.81 h1.52
  text "-" at 362.019,100.81 h1.52
  text "20" at 240.894,97 h1.52
  text "1,200mm (47,24mil)" at 257.4,97 h1.52
  text "PTH" at 287.109,97 h1.52
  text "Round" at 299.959,97 h1.52
  text "Pad" at 318.597,97 h1.52
  text "-" at 333.579,97 h1.52
  text "-" at 362.019,97 h1.52
  text "H" at 227.306,96.746 h1.69
  text "2" at 240.894,93.19 h1.52
  text "1,500mm (59,06mil)" at 257.4,93.19 h1.52
  text "NPTH" at 287.109,93.19 h1.52
  text "Round" at 299.959,93.19 h1.52
  text "Pad" at 318.597,93.19 h1.52
  text "-" at 333.579,93.19 h1.52
  text "-" at 362.019,93.19 h1.52
  text "2" at 240.894,89.38 h1.52
  text "1,700mm (66,93mil)" at 257.4,89.38 h1.52
  text "PTH" at 287.109,89.38 h1.52
  text "Round" at 299.959,89.38 h1.52
  text "Pad" at 318.597,89.38 h1.52
  text "-" at 333.579,89.38 h1.52
  text "-" at 362.019,89.38 h1.52
  text "4" at 240.894,85.57 h1.52
  text "2,000mm (78,74mil)" at 257.4,85.57 h1.52
  text "NPTH" at 287.109,85.57 h1.52
  text "Round" at 299.959,85.57 h1.52
  text "Pad" at 318.597,85.57 h1.52
  text "-" at 333.579,85.57 h1.52
  text "-" at 362.019,85.57 h1.52
  text "1" at 240.894,81.76 h1.52
  text "2,100mm (82,68mil)" at 257.4,81.76 h1.52
  text "NPTH" at 287.109,81.76 h1.52
  text "Round" at 299.959,81.76 h1.52
  text "Pad" at 318.597,81.76 h1.52
  text "-" at 333.579,81.76 h1.52
  text "-" at 362.019,81.76 h1.52
  text "2" at 240.894,77.95 h1.52
  text "2,150mm (84,65mil)" at 257.4,77.95 h1.52
  text "NPTH" at 287.109,77.95 h1.52
  text "Round" at 299.959,77.95 h1.52
  text "Pad" at 318.597,77.95 h1.52
  text "-" at 333.579,77.95 h1.52
  text "-" at 362.019,77.95 h1.52
  text "8" at 240.894,74.14 h1.52
  text "2,330mm (91,73mil)" at 257.4,74.14 h1.52
  text "PTH" at 287.109,74.14 h1.52
  text "Round" at 299.959,74.14 h1.52
  text "Pad" at 318.597,74.14 h1.52
  text "-" at 333.579,74.14 h1.52
  text "-" at 362.019,74.14 h1.52
  text "2" at 240.894,70.33 h1.52
  text "3,200mm (125,98mil)" at 257.4,70.33 h1.52
  text "NPTH" at 287.109,70.33 h1.52
  text "Round" at 299.959,70.33 h1.52
  text "Pad" at 318.597,70.33 h1.52
  text "-" at 333.579,70.33 h1.52
  text "-" at 362.019,70.33 h1.52
  text "4" at 240.894,66.52 h1.52
  text "3,200mm (125,98mil)" at 257.4,66.52 h1.52
  text "PTH" at 287.109,66.52 h1.52
  text "Round" at 299.959,66.52 h1.52
  text "Pad" at 318.597,66.52 h1.52
  text "-" at 333.579,66.52 h1.52
  text "-" at 362.019,66.52 h1.52
  text "4" at 240.894,62.71 h1.52
  text "3,300mm (129,92mil)" at 257.4,62.71 h1.52
  text "PTH" at 287.109,62.71 h1.52
  text "Round" at 299.959,62.71 h1.52
  text "Pad" at 318.597,62.71 h1.52
  text "-" at 333.579,62.71 h1.52
  text "-" at 362.019,62.71 h1.52
  text "9" at 240.894,58.9 h1.52
  text "3,500mm (137,80mil)" at 257.4,58.9 h1.52
  text "PTH" at 287.109,58.9 h1.52
  text "Round" at 299.959,58.9 h1.52
  text "Pad" at 318.597,58.9 h1.52
  text "-" at 333.579,58.9 h1.52
  text "-" at 362.019,58.9 h1.52
  text "1955 Total" at 240.894,55.09 h1.52
  text "Slot definitions :" at 228.045,51.408 h1.52
  text "Routed Path Length" at 254.276,51.408 h1.52
  text "= Calculated from tool start centre position to tool end centre position." at 282.283,51.408 h1.52
  text "Hole Length" at 254.276,48.868 h1.52
  text "= Routed Path Length + Tool Size = Slot length as defined in the PCB layout" at 271.873,48.868 h1.52
  text "FAB DRAWING & DRILL LEGEND" at 82.113,-20.338 h1.9
Mechanical 27:
  the board outline again, w0.1
  text "ASSEMBLY DRAWING, (PRIMARY)" at 81.56,-20.33 h1.9
Mechanical 30:
  the board outline again, w0.1
  text "ASSEMBLY DRAWING, (SECONDARY)" at 125.786,-20.33 h1.7

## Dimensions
0,250 to 208,250 on Drill Drawing
0,250 to 0,0 on Drill Drawing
